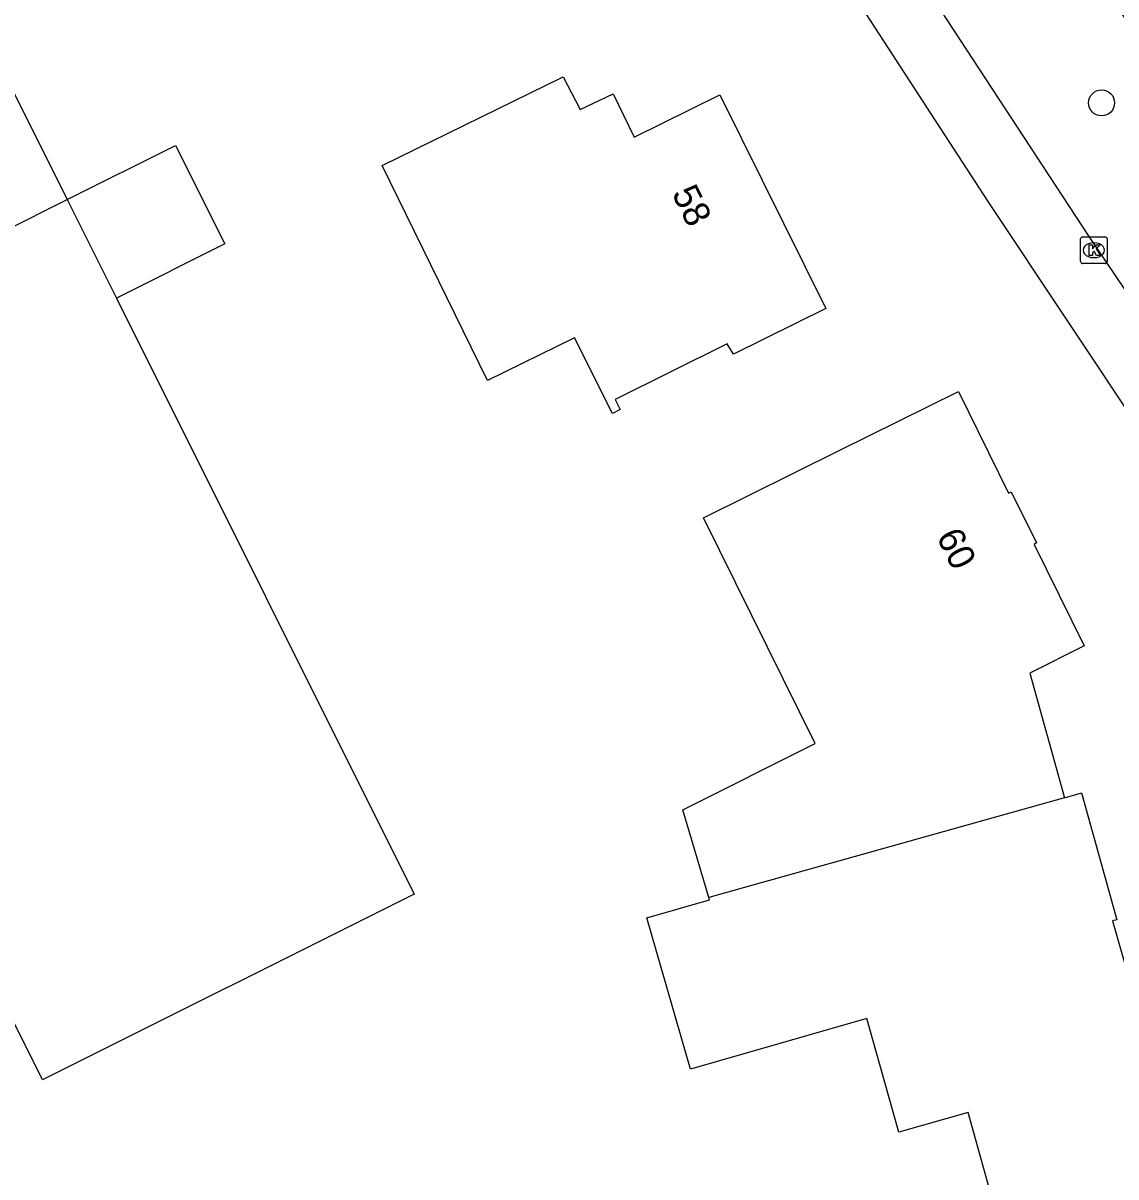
# Model space of a CAD drawing. Extents: x 157793 to 159380, y 380882 to 382313.
# Drawn here: x 158151.07 to 158192.17, y 381421.49 to 381464.87 of the extents above; entities that cross this region are included whole.
import ezdxf

# ---------------------------------------------------------------- set-up
doc = ezdxf.new("R2010")
doc.units = 0
for name, color, linetype in [('IMGEO_Boom', 7, 'Continuous'), ('IMGEO_Kolk', 7, 'Continuous'), ('IMGEO_Pand', 7, 'Continuous'), ('IMGEO_Pand_nummerreeks', 7, 'Continuous'), ('IMGEO_Voetpad_open', 7, 'Continuous')]:
    doc.layers.add(name, color=color, linetype=linetype)

msp = doc.modelspace()

# ---------------------------------------------------------------- linework, layer by layer
at = {"layer": 'IMGEO_Boom'}
msp.add_circle((158191.627, 381461.867), 0.489, dxfattribs=at)
at = {"layer": 'IMGEO_Kolk'}
for p, q in [((158190.837, 381455.904), (158190.837, 381456.756)), ((158190.912, 381456.83), (158191.764, 381456.83)), ((158191.325, 381456.61), (158191.35, 381456.61)), ((158191.838, 381456.756), (158191.838, 381455.904)), ((158191.348, 381456.05), (158191.323, 381456.05)), ((158191.764, 381455.83), (158190.912, 381455.83))]:
    msp.add_line(p, q, dxfattribs=at)
for points in [[(158190.837, 381455.904), (158190.837, 381456.756)], [(158190.912, 381456.83), (158191.764, 381456.83)], [(158191.158, 381456.53), (158191.281, 381456.53), (158191.281, 381456.379), (158191.411, 381456.53), (158191.575, 381456.53), (158191.429, 381456.379), (158191.582, 381456.13), (158191.43, 381456.13), (158191.345, 381456.294), (158191.281, 381456.227), (158191.281, 381456.13), (158191.158, 381456.13), (158191.158, 381456.53)], [(158191.838, 381456.756), (158191.838, 381455.904)], [(158191.764, 381455.83), (158190.912, 381455.83)]]:
    msp.add_lwpolyline(points, dxfattribs=at)
for centre, start, end in [((158190.914, 381456.754), 91.552, 178.448), ((158190.914, 381456.754), 91.552, 178.448), ((158191.762, 381456.754), 1.552, 88.448), ((158191.762, 381456.754), 1.552, 88.448), ((158190.914, 381455.906), 181.552, 268.448), ((158190.914, 381455.906), 181.552, 268.448), ((158191.762, 381455.906), 271.552, 358.448), ((158191.762, 381455.906), 271.552, 358.448)]:
    msp.add_arc(centre, 0.0765, start, end, dxfattribs=at)
for centre, major_axis, ratio, start_param, end_param in [((158191.324, 381456.33), (-0.387, 0.002), 0.722429, 4.712389, 7.853982), ((158191.349, 381456.33), (-0.39, 0.002), 0.717154, 1.570796, 4.712389)]:
    msp.add_ellipse(centre, major_axis=major_axis, ratio=ratio, start_param=start_param, end_param=end_param, dxfattribs=at)
at = {"layer": 'IMGEO_Pand'}
for points in [[(158138.549, 381473.356), (158143.854, 381475.996), (158152.732, 381458.23)], [(158164.573, 381459.518), (158171.388, 381462.846), (158172.022, 381461.614), (158173.263, 381462.206), (158174.05, 381460.583), (158177.272, 381462.167), (158181.257, 381454.14), (158177.783, 381452.419), (158177.555, 381452.816), (158173.342, 381450.722), (158173.527, 381450.336), (158173.241, 381450.187), (158171.804, 381453.032), (158168.533, 381451.43), (158164.573, 381459.518)], [(158152.732, 381458.23), (158156.81, 381460.268), (158158.66, 381456.564), (158154.582, 381454.526)], [(158112.296, 381437.92), (158152.732, 381458.23)], [(158152.732, 381458.23), (158154.582, 381454.526)], [(158154.582, 381454.526), (158165.775, 381432.125), (158151.804, 381425.141), (158145.928, 381436.906), (158124.878, 381426.406), (158120.403, 381424.174), (158119.541, 381425.901), (158112.381, 381422.33), (158108.81, 381429.501), (158107.949, 381429.043)], [(158176.859, 381432.003), (158175.885, 381435.291), (158180.861, 381437.788), (158176.662, 381446.276), (158181.765, 381448.8), (158186.246, 381451.017), (158188.13, 381447.198), (158188.228, 381447.245), (158189.179, 381445.333), (158189.097, 381445.262), (158190.974, 381441.461), (158188.929, 381440.437), (158190.228, 381435.75)], [(158190.228, 381435.75), (158190.873, 381435.931), (158192.195, 381431.163), (158192.041, 381431.12), (158192.719, 381428.751), (158194.735, 381429.314), (158196.364, 381423.526), (158194.591, 381423.048), (158195.786, 381418.708), (158193.237, 381417.99), (158193.644, 381416.52), (158190.816, 381415.733), (158188.828, 381415.18), (158186.44, 381414.515), (158185.227, 381418.828), (158187.828, 381419.559), (158186.605, 381423.911), (158184.004, 381423.18), (158182.803, 381427.451), (158176.169, 381425.544), (158174.534, 381431.231), (158176.887, 381431.907), (158176.859, 381432.003)], [(158190.228, 381435.75), (158176.859, 381432.003)]]:
    msp.add_lwpolyline(points, dxfattribs=at)
at = {"layer": 'IMGEO_Voetpad_open'}
for points in [[(158196.197, 381444.89), (158187.383, 381458.121), (158179.308, 381470.565), (158168.261, 381487.773), (158162.146, 381497.834)], [(158189.292, 381469.869), (158184.614, 381466.823), (158191.129, 381456.883), (158198.958, 381445.276), (158200.372, 381442.689), (158206.681, 381444.18), (158201.324, 381451.912), (158189.292, 381469.869)]]:
    msp.add_lwpolyline(points, dxfattribs=at)

# ---------------------------------------------------------------- texts
at = {"layer": 'IMGEO_Pand_nummerreeks'}
for s, rotation, p in [('58', 296.4021, (158175.45, 381458.465)), ('60', 296.4475, (158185.4, 381445.565))]:
    msp.add_text(s, height=1, rotation=rotation, dxfattribs=at).set_placement(p)

doc.saveas('drawing.dxf')
